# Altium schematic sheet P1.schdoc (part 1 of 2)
size 743 x 524 mm; Symbol: Drawing-Symbol_A4; @Project Name: pcbgolf; @Page Count: 1; @Update Date: 2026-09-13; @Create Date: 2026-09-12; @Schematic Name: Schematic1; @Page No: 1; @Page Name: P1; Company: EasyEDA.com; Version: eda image copy occupy; Page Size: A4; @Create Time: 18:56:01; @Update Time: 00:26:01; Border: 1; Width: 2925; Height: 2063; Region Start: 1; X Region Count: 6; Y Region Count: 4; Blade Width: 10; Title Block Position: 3; @Board Name: Board1; Device: Drawing-Symbol_A4
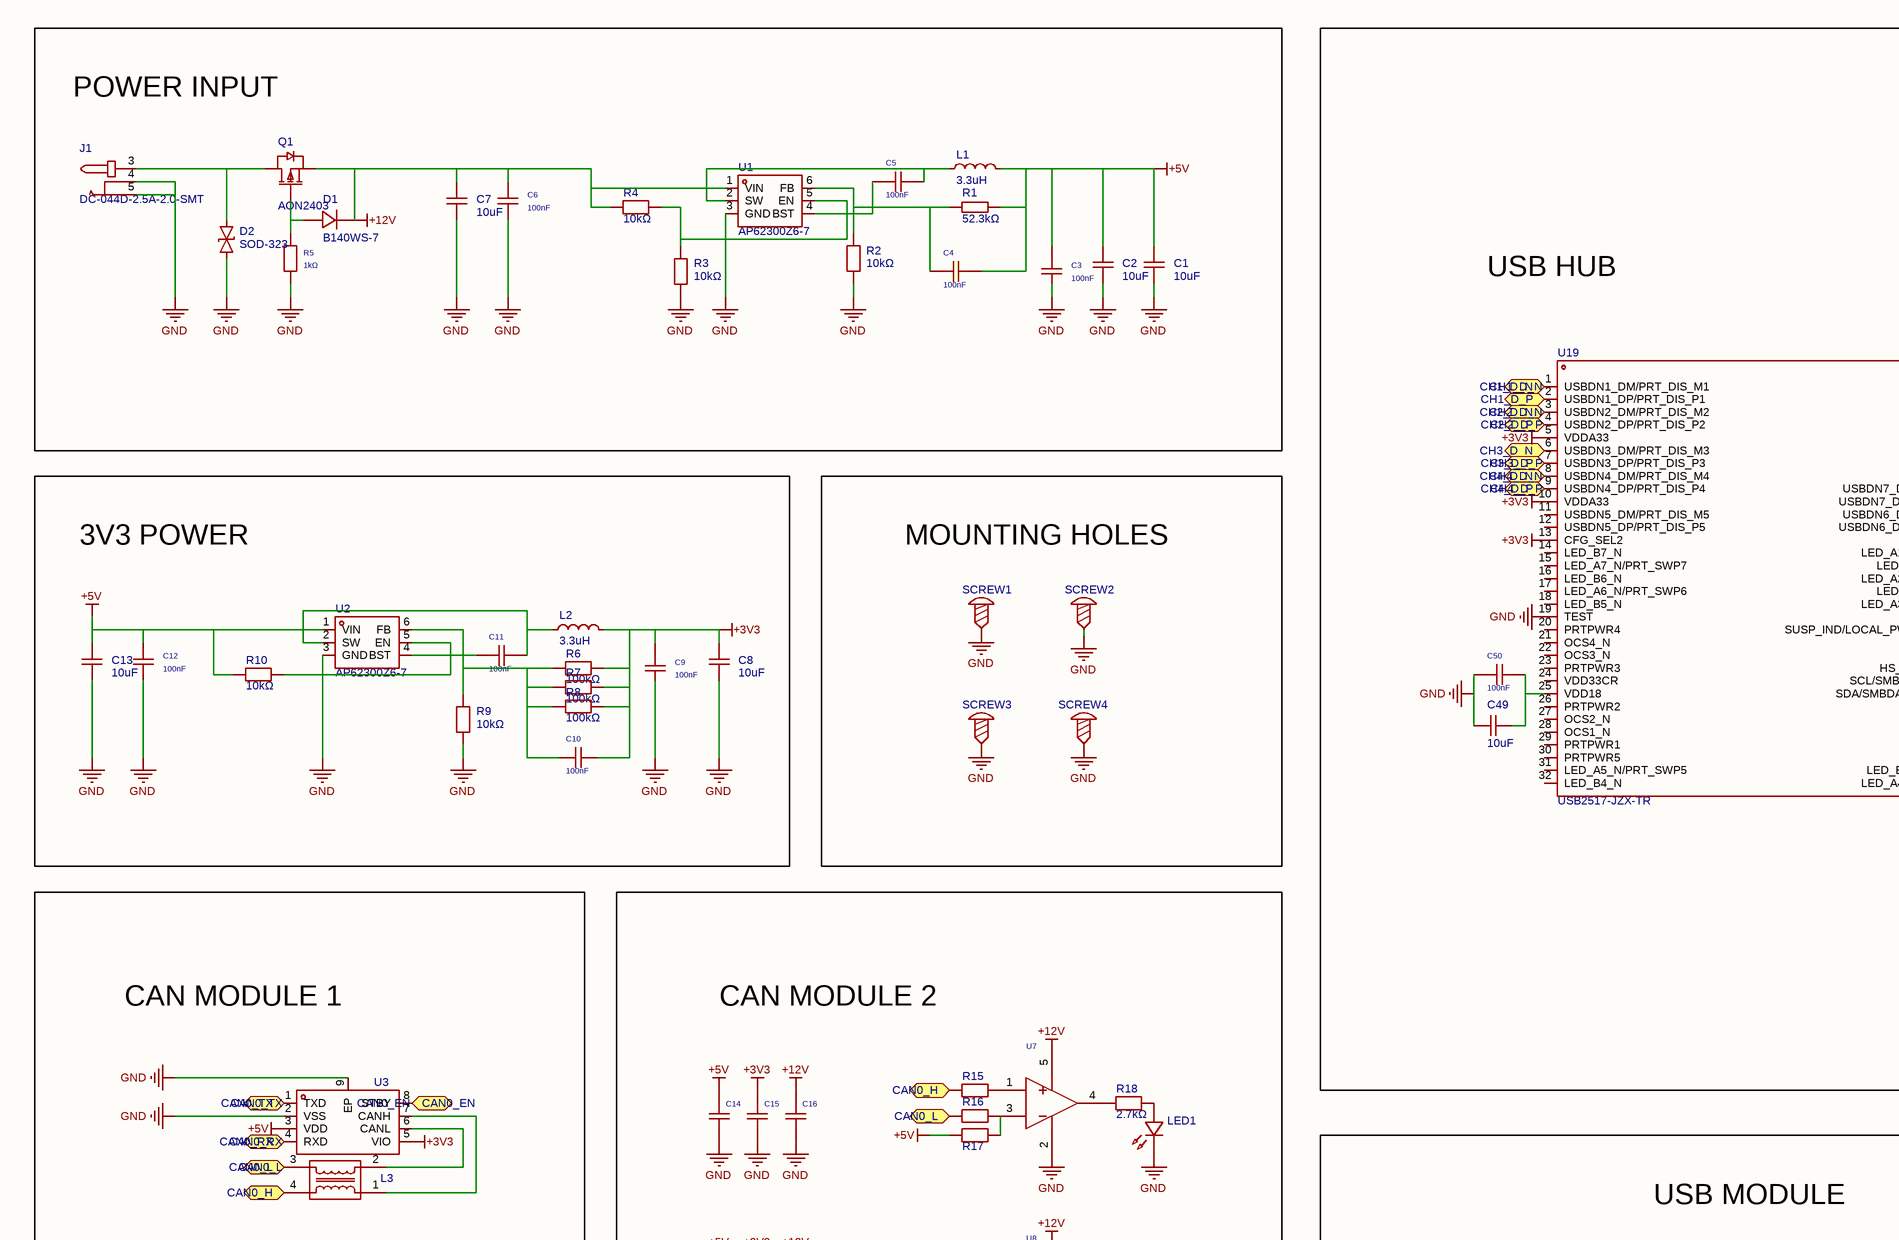
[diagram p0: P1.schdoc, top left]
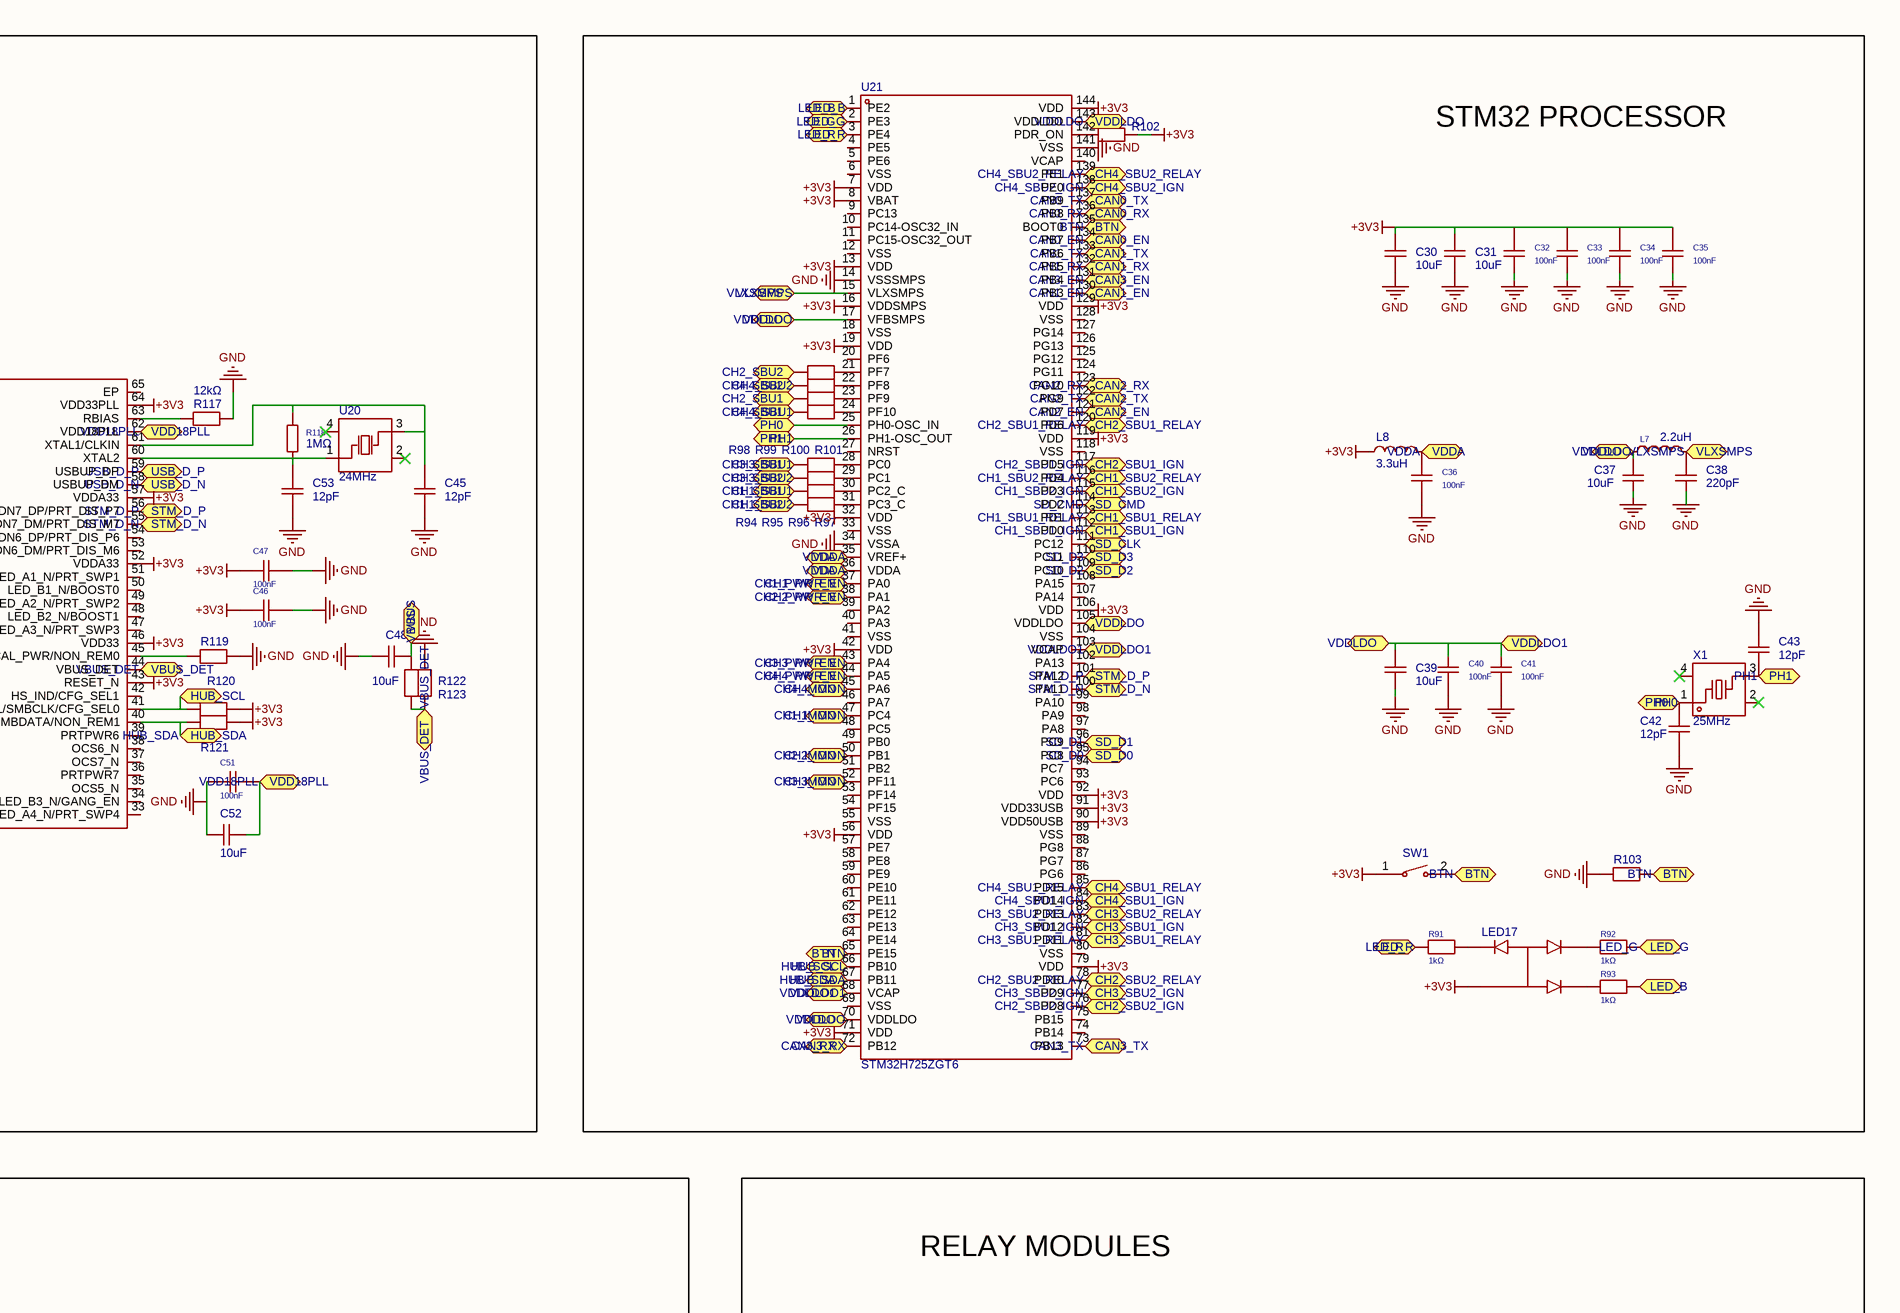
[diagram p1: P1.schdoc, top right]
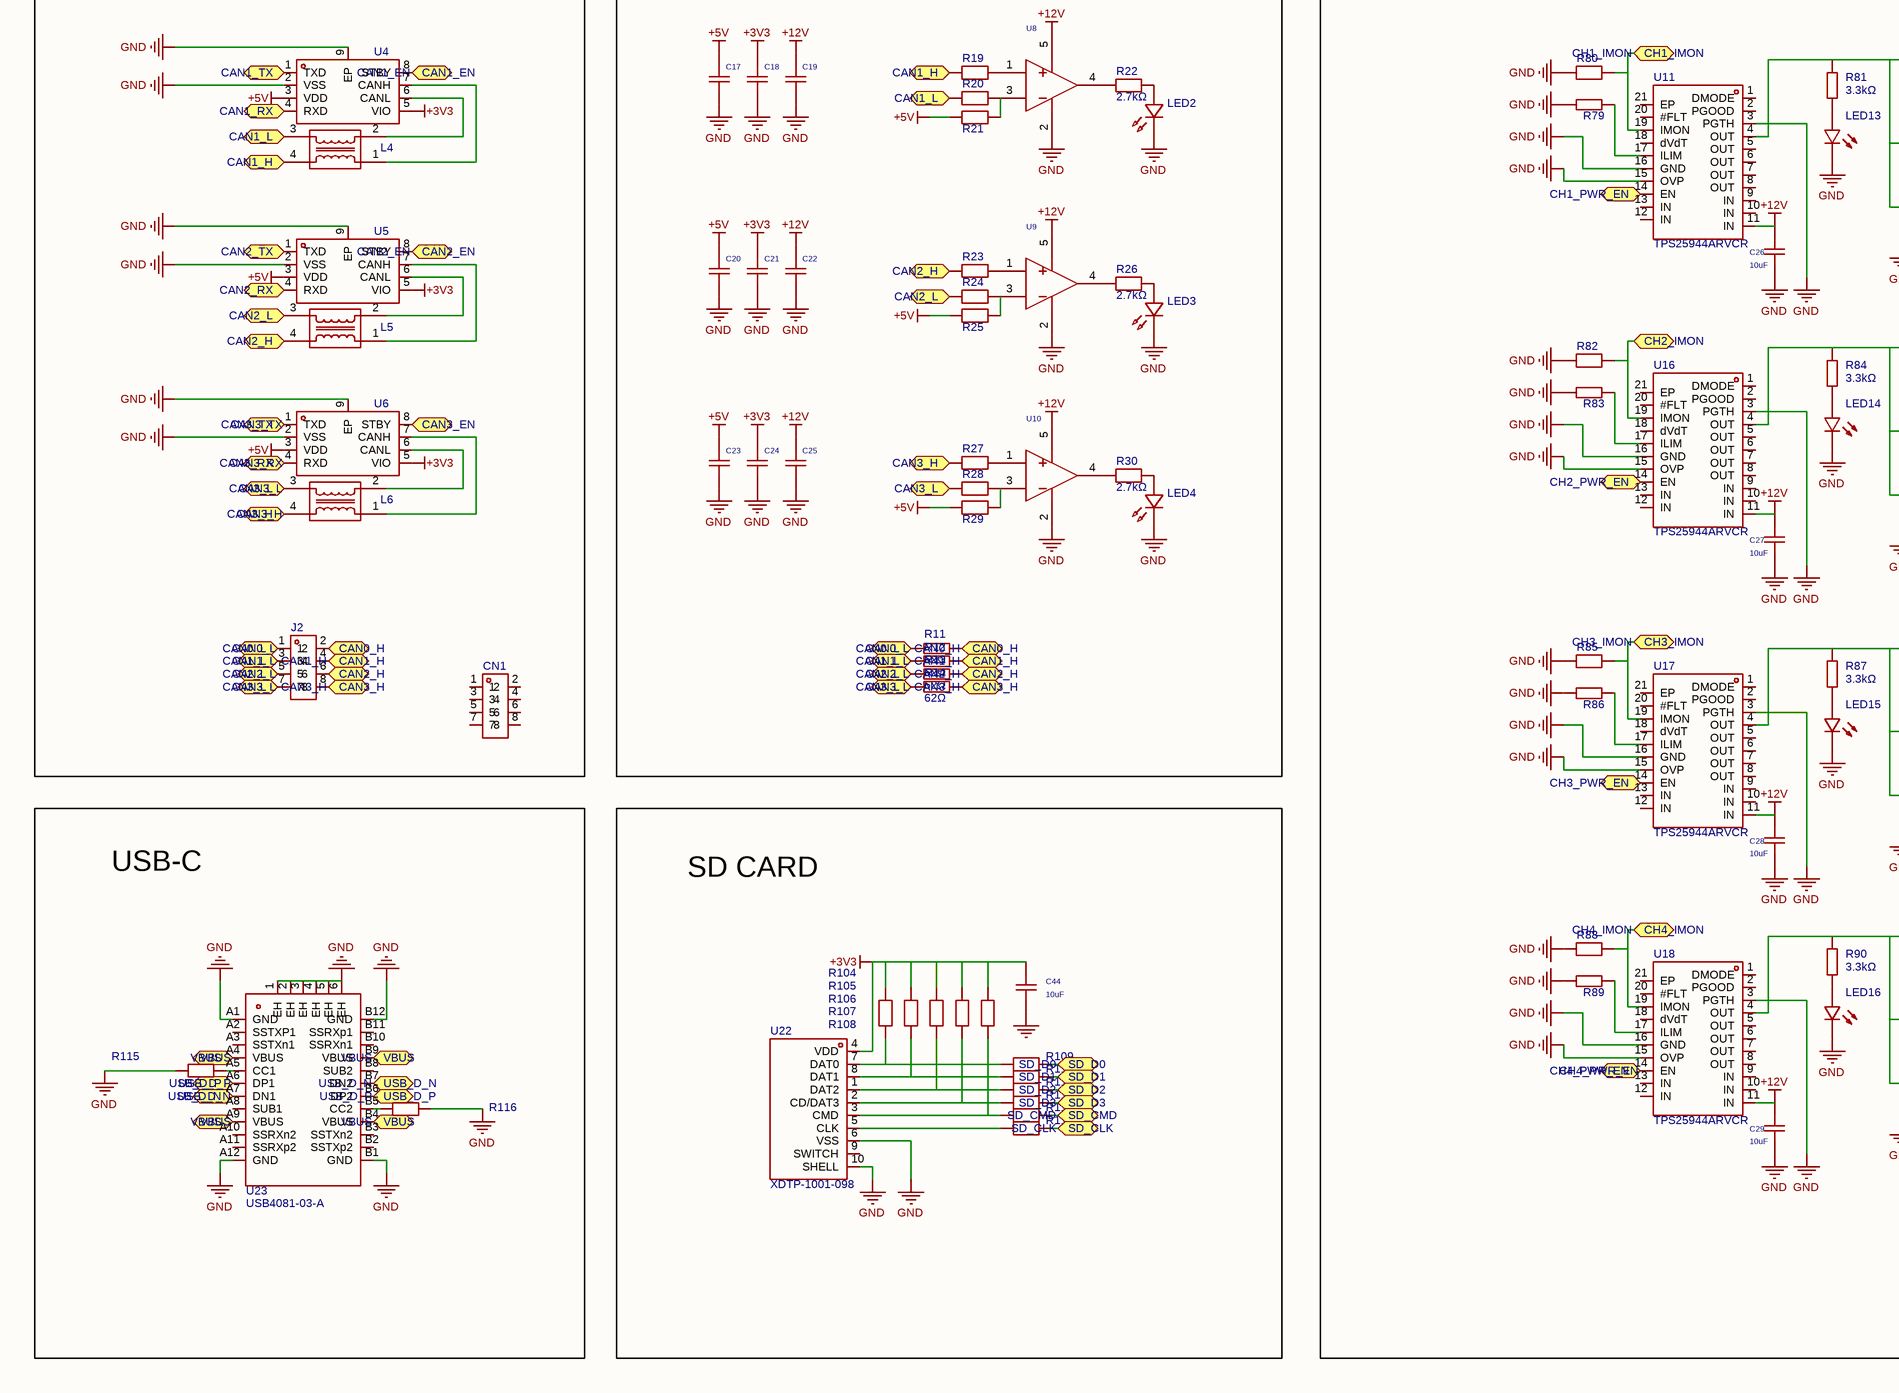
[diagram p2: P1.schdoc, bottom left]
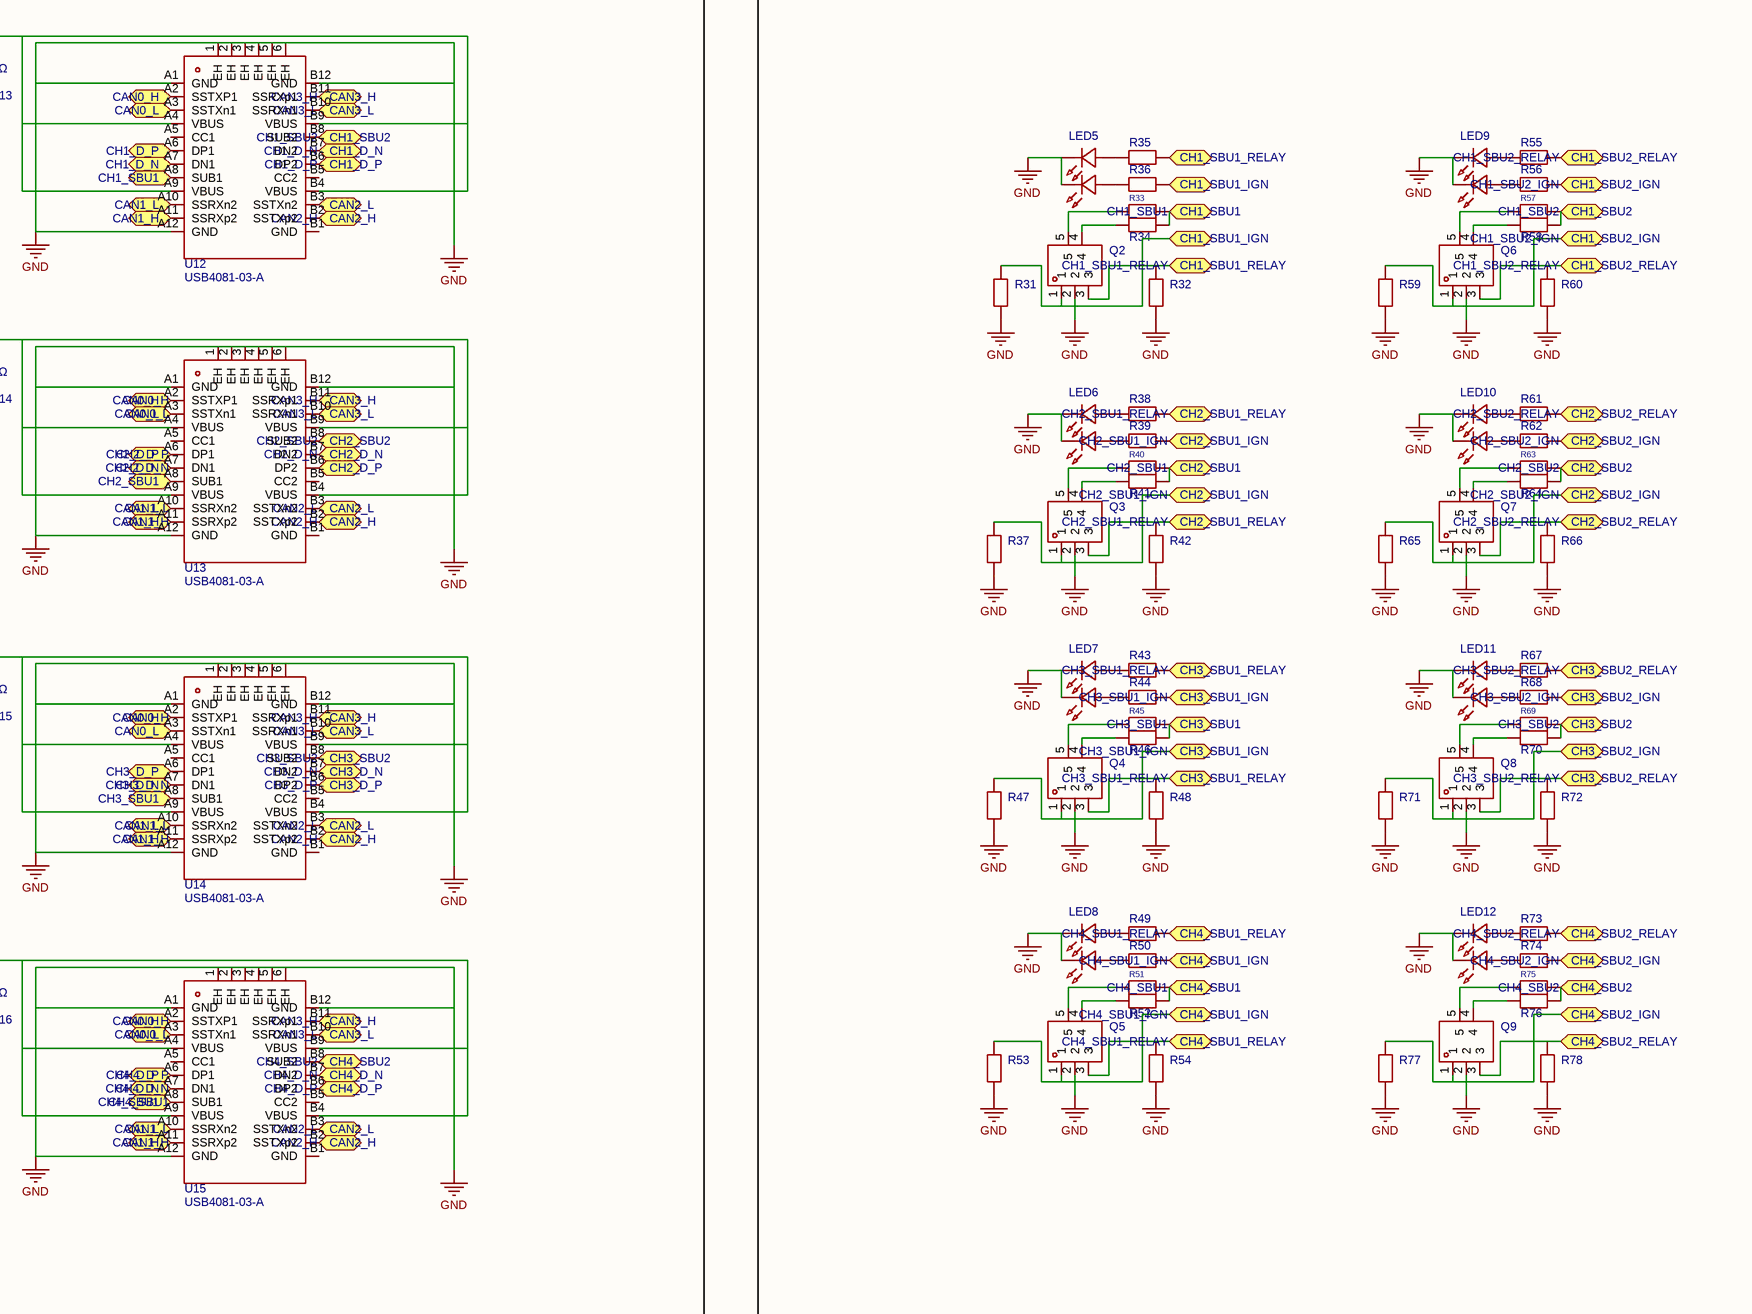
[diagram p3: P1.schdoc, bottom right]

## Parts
C1  10uF  [C0402]
C2  10uF  [C0402]
C3  100nF  [C0201]
C4  100nF  [C0201]
C5  100nF  [C0201]
C6  100nF  [C0201]
C7  10uF  [C0402]
C8  10uF  [C0402]
C9  100nF  [C0201]
C10  100nF  [C0201]
C11  100nF  [C0201]
C12  100nF  [C0201]
C13  10uF  [C0402]
C14  100nF  [C0201]  (value not drawn)
C15  100nF  [C0201]  (value not drawn)
C16  100nF  [C0201]  (value not drawn)
C17  100nF  [C0201]  (value not drawn)
C18  100nF  [C0201]  (value not drawn)
C19  100nF  [C0201]  (value not drawn)
C20  100nF  [C0201]  (value not drawn)
C21  100nF  [C0201]  (value not drawn)
C22  100nF  [C0201]  (value not drawn)
C23  100nF  [C0201]  (value not drawn)
C24  100nF  [C0201]  (value not drawn)
C25  100nF  [C0201]  (value not drawn)
C26  10uF  [C0201]
C27  10uF  [C0201]
C28  10uF  [C0201]
C29  10uF  [C0201]
C30  10uF  [C0402]
C31  10uF  [C0402]
C32  100nF  [C0201]
C33  100nF  [C0201]
C34  100nF  [C0201]
C35  100nF  [C0201]
C36  100nF  [C0201]
C37  10uF  [C0402]
C38  220pF  [C0201]
C39  10uF  [C0402]
C40  100nF  [C0201]
C41  100nF  [C0201]
C42  12pF  [C0201]
C43  12pF  [C0201]
C44  10uF  [C0201]
C45  12pF  [C0201]
C46  100nF  [C0201]
C47  100nF  [C0201]
C48  10uF  [C0402]
C49  10uF  [C0402]
C50  100nF  [C0201]
C51  100nF  [C0201]
C52  10uF  [C0402]
C53  12pF  [C0201]
CN1  DIP2*4P双排弯脚排母间距2.0mm塑长6.35塑高4.0ROHS散装  [HDR-TH_8P-P2.54_C9900016769]  (value not drawn)
D1  B140WS-7  [SOD-323_L1.8-W1.3-LS2.5-RD]
D2  SOD-323  [SOD-323_L1.7-W1.3-LS2.5-BI]
J1  DC-044D-2.5A-2.0-SMT  [DC-IN-SMD_DC-044D-2.5A-2.0-SMT]
J2  SSQ-104-04-T-D  [HDR-TH_8P-P2.54_SSW-104-23-F-D]  (value not drawn)
L1  3.3uH  [L0603]
L2  3.3uH  [L0603]
L3  ACM2012-900-2P-T001  [FILTER-SMD_4P-L2.0-W1.2-TL_ACM2012E]  (value not drawn)
L4  ACM2012-900-2P-T001  [FILTER-SMD_4P-L2.0-W1.2-TL_ACM2012E]  (value not drawn)
L5  ACM2012-900-2P-T001  [FILTER-SMD_4P-L2.0-W1.2-TL_ACM2012E]  (value not drawn)
L6  ACM2012-900-2P-T001  [FILTER-SMD_4P-L2.0-W1.2-TL_ACM2012E]  (value not drawn)
L7  2.2uH  [L0402]
L8  3.3uH  [L0603]
LED1  APHHS1005LSECK/J3-PF  [LED0402-RD_RED]  (value not drawn)
LED2  APHHS1005LSECK/J3-PF  [LED0402-RD_RED]  (value not drawn)
LED3  APHHS1005LSECK/J3-PF  [LED0402-RD_RED]  (value not drawn)
LED4  APHHS1005LSECK/J3-PF  [LED0402-RD_RED]  (value not drawn)
LED5  HSMF-C163  [LED-SMD_L1.6-W0.8_HSMF-C163]  (value not drawn)
LED6  HSMF-C163  [LED-SMD_L1.6-W0.8_HSMF-C163]  (value not drawn)
LED7  HSMF-C163  [LED-SMD_L1.6-W0.8_HSMF-C163]  (value not drawn)
LED8  HSMF-C163  [LED-SMD_L1.6-W0.8_HSMF-C163]  (value not drawn)
LED9  HSMF-C163  [LED-SMD_L1.6-W0.8_HSMF-C163]  (value not drawn)
LED10  HSMF-C163  [LED-SMD_L1.6-W0.8_HSMF-C163]  (value not drawn)
LED11  HSMF-C163  [LED-SMD_L1.6-W0.8_HSMF-C163]  (value not drawn)
LED12  HSMF-C163  [LED-SMD_L1.6-W0.8_HSMF-C163]  (value not drawn)
LED13  SLED-0603-H0_8MM  [LED0603-R-RD_RED]  (value not drawn)
LED14  SLED-0603-H0_8MM  [LED0603-R-RD_RED]  (value not drawn)
LED15  SLED-0603-H0_8MM  [LED0603-R-RD_RED]  (value not drawn)
LED16  SLED-0603-H0_8MM  [LED0603-R-RD_RED]  (value not drawn)
LED17  TZ1615RGB3U-Common Yang  [LED-SMD_TZ1615RGB3U-COMMON-YANG]  (value not drawn)
Q1  AON2403  [DFN-6_L2.0-W2.0-P0.65-BL-EP-1]
Q2  QS5K2TR  [SOT-23-5_L2.9-W1.6-P0.95-LS2.8-TL]  (value not drawn)
Q3  QS5K2TR  [SOT-23-5_L2.9-W1.6-P0.95-LS2.8-TL]  (value not drawn)
Q4  QS5K2TR  [SOT-23-5_L2.9-W1.6-P0.95-LS2.8-TL]  (value not drawn)
Q5  QS5K2TR  [SOT-23-5_L2.9-W1.6-P0.95-LS2.8-TL]  (value not drawn)
Q6  QS5K2TR  [SOT-23-5_L2.9-W1.6-P0.95-LS2.8-TL]  (value not drawn)
Q7  QS5K2TR  [SOT-23-5_L2.9-W1.6-P0.95-LS2.8-TL]  (value not drawn)
Q8  QS5K2TR  [SOT-23-5_L2.9-W1.6-P0.95-LS2.8-TL]  (value not drawn)
Q9  QS5K2TR  [SOT-23-5_L2.9-W1.6-P0.95-LS2.8-TL]  (value not drawn)
R1  52.3kΩ  [R0201]
R2  10kΩ  [R0201]
R3  10kΩ  [R0201]
R4  10kΩ  [R0201]
R5  1kΩ  [R0201]
R6  100kΩ  [R0201]
R7  100kΩ  [R0201]
R8  100kΩ  [R0201]
R9  10kΩ  [R0201]
R10  10kΩ  [R0201]
R11  62Ω  [R0201]
R12  62Ω  [R0201]
R13  62Ω  [R0201]
R14  62Ω  [R0201]
R15  10kΩ  [R0201]  (value not drawn)
R16  10kΩ  [R0201]  (value not drawn)
R17  100kΩ  [R0201]  (value not drawn)
R18  2.7kΩ  [R0201]
R19  10kΩ  [R0201]  (value not drawn)
R20  10kΩ  [R0201]  (value not drawn)
R21  100kΩ  [R0201]  (value not drawn)
R22  2.7kΩ  [R0201]
R23  10kΩ  [R0201]  (value not drawn)
R24  10kΩ  [R0201]  (value not drawn)
R25  100kΩ  [R0201]  (value not drawn)
R26  2.7kΩ  [R0201]
R27  10kΩ  [R0201]  (value not drawn)
R28  10kΩ  [R0201]  (value not drawn)
R29  100kΩ  [R0201]  (value not drawn)
R30  2.7kΩ  [R0201]
R31  10kΩ  [R0201]  (value not drawn)
R32  10kΩ  [R0201]  (value not drawn)
R33  1kΩ  [R0201]  (value not drawn)
R34  100Ω  [R0201]  (value not drawn)
R35  100Ω  [R0201]  (value not drawn)
R36  100Ω  [R0201]  (value not drawn)
R37  10kΩ  [R0201]  (value not drawn)
R38  100Ω  [R0201]  (value not drawn)
R39  100Ω  [R0201]  (value not drawn)
R40  1kΩ  [R0201]  (value not drawn)
R41  100Ω  [R0201]  (value not drawn)
R42  10kΩ  [R0201]  (value not drawn)
R43  100Ω  [R0201]  (value not drawn)
R44  100Ω  [R0201]  (value not drawn)
R45  1kΩ  [R0201]  (value not drawn)
R46  100Ω  [R0201]  (value not drawn)
R47  10kΩ  [R0201]  (value not drawn)
R48  10kΩ  [R0201]  (value not drawn)
R49  100Ω  [R0201]  (value not drawn)
R50  100Ω  [R0201]  (value not drawn)
R51  1kΩ  [R0201]  (value not drawn)
R52  100Ω  [R0201]  (value not drawn)
R53  10kΩ  [R0201]  (value not drawn)
R54  10kΩ  [R0201]  (value not drawn)
R55  100Ω  [R0201]  (value not drawn)
R56  100Ω  [R0201]  (value not drawn)
R57  1kΩ  [R0201]  (value not drawn)
R58  100Ω  [R0201]  (value not drawn)
R59  10kΩ  [R0201]  (value not drawn)
R60  10kΩ  [R0201]  (value not drawn)
R61  100Ω  [R0201]  (value not drawn)
R62  100Ω  [R0201]  (value not drawn)
R63  1kΩ  [R0201]  (value not drawn)
R64  100Ω  [R0201]  (value not drawn)
R65  10kΩ  [R0201]  (value not drawn)
R66  10kΩ  [R0201]  (value not drawn)
R67  100Ω  [R0201]  (value not drawn)
R68  100Ω  [R0201]  (value not drawn)
R69  1kΩ  [R0201]  (value not drawn)
R70  100Ω  [R0201]  (value not drawn)
R71  10kΩ  [R0201]  (value not drawn)
R72  10kΩ  [R0201]  (value not drawn)
R73  100Ω  [R0201]  (value not drawn)
R74  100Ω  [R0201]  (value not drawn)
R75  1kΩ  [R0201]  (value not drawn)
R76  100Ω  [R0201]  (value not drawn)
R77  10kΩ  [R0201]  (value not drawn)
R78  10kΩ  [R0201]  (value not drawn)
R79  28kΩ  [R0201]  (value not drawn)
R80  33kΩ  [R0201]  (value not drawn)
R81  3.3kΩ  [R0201]
R82  33kΩ  [R0201]  (value not drawn)
R83  28kΩ  [R0201]  (value not drawn)
R84  3.3kΩ  [R0201]
R85  33kΩ  [R0201]  (value not drawn)
R86  28kΩ  [R0201]  (value not drawn)
R87  3.3kΩ  [R0201]
R88  33kΩ  [R0201]  (value not drawn)
R89  28kΩ  [R0201]  (value not drawn)
R90  3.3kΩ  [R0201]
R91  1kΩ  [R0201]
R92  1kΩ  [R0201]
R93  1kΩ  [R0201]
R94  100kΩ  [R0201]  (value not drawn)
R95  100kΩ  [R0201]  (value not drawn)
R96  100kΩ  [R0201]  (value not drawn)
R97  100kΩ  [R0201]  (value not drawn)
R98  100kΩ  [R0201]  (value not drawn)
R99  100kΩ  [R0201]  (value not drawn)
R100  100kΩ  [R0201]  (value not drawn)
R101  100kΩ  [R0201]  (value not drawn)
R102  10kΩ  [R0201]  (value not drawn)
R103  10kΩ  [R0201]  (value not drawn)
R104  10kΩ  [R0201]  (value not drawn)
R105  10kΩ  [R0201]  (value not drawn)
R106  10kΩ  [R0201]  (value not drawn)
R107  10kΩ  [R0201]  (value not drawn)
R108  10kΩ  [R0201]  (value not drawn)
R109  0Ω  [R0201]  (value not drawn)
R110  0Ω  [R0201]  (value not drawn)
R111  0Ω  [R0201]  (value not drawn)
R112  0Ω  [R0201]  (value not drawn)
R113  0Ω  [R0201]  (value not drawn)
R114  0Ω  [R0201]  (value not drawn)
R115  10kΩ  [R0201]  (value not drawn)
R116  10kΩ  [R0201]  (value not drawn)
R117  12kΩ  [R0201]
R118  1MΩ  [R0402]
R119  10kΩ  [R0201]  (value not drawn)
R120  10kΩ  [R0201]  (value not drawn)
R121  10kΩ  [R0201]  (value not drawn)
R122  100kΩ  [R0201]  (value not drawn)
R123  100kΩ  [R0201]  (value not drawn)
SCREW1  (no value)  [Screw-Hole-M2]
SCREW2  (no value)  [Screw-Hole-M2]
SCREW3  (no value)  [Screw-Hole-M2]
SCREW4  (no value)  [Screw-Hole-M2]
SW1  TS-1809-T20  [SW-SMD_L3.9-W2.9-LS4.8SWQC_SPST]  (value not drawn)
U1  AP62300Z6-7  [SOT-563-6_L1.6-W1.2-P0.50-LS1.6-BL]
U2  AP62300Z6-7  [SOT-563-6_L1.6-W1.2-P0.50-LS1.6-BL]
U3  MCP2542FDT-E/MNY  [TDFN-8_L3.0-W2.0-P0.50-TL-EP]  (value not drawn)
U4  MCP2542FDT-E/MNY  [TDFN-8_L3.0-W2.0-P0.50-TL-EP]  (value not drawn)
U5  MCP2542FDT-E/MNY  [TDFN-8_L3.0-W2.0-P0.50-TL-EP]  (value not drawn)
U6  MCP2542FDT-E/MNY  [TDFN-8_L3.0-W2.0-P0.50-TL-EP]  (value not drawn)
U7  NCS20071XV53T2G  [SOT-553-5_L1.6-W1.2-P0.50-LS1.6-BL]  (value not drawn)
U8  NCS20071XV53T2G  [SOT-553-5_L1.6-W1.2-P0.50-LS1.6-BL]  (value not drawn)
U9  NCS20071XV53T2G  [SOT-553-5_L1.6-W1.2-P0.50-LS1.6-BL]  (value not drawn)
U10  NCS20071XV53T2G  [SOT-553-5_L1.6-W1.2-P0.50-LS1.6-BL]  (value not drawn)
U11  TPS25944ARVCR  [WQFN-20_L4.0-W3.0-P0.50-BL-EP]
U12  USB4081-03-A  [USB-SMD_USB4081-03-A]
U13  USB4081-03-A  [USB-SMD_USB4081-03-A]
U14  USB4081-03-A  [USB-SMD_USB4081-03-A]
U15  USB4081-03-A  [USB-SMD_USB4081-03-A]
U16  TPS25944ARVCR  [WQFN-20_L4.0-W3.0-P0.50-BL-EP]
U17  TPS25944ARVCR  [WQFN-20_L4.0-W3.0-P0.50-BL-EP]
U18  TPS25944ARVCR  [WQFN-20_L4.0-W3.0-P0.50-BL-EP]
U19  USB2517-JZX-TR  [QFN-64_L9.0-W9.0-P0.50-BL-EP4.8]
U20  24MHz  [CRYSTAL-SMD_4P-L3.2-W2.5-BL]
U21  STM32H725ZGT6  [LQFP-144_L20.0-W20.0-P0.50-LS22.0-BL]
U22  XDTP-1001-098  [MICRO-SD-SMD_XDTP-1001-098]
U23  USB4081-03-A  [USB-SMD_USB4081-03-A]
X1  25MHz  [CRYSTAL-SMD_4P-L2.0-W1.6-BL]

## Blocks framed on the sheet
POWER INPUT: C1-C7 D1 D2 J1 L1 Q1 R1-R5 U1
USB HUB: C45-C53 R117-R123 U19 U20
STM32 PROCESSOR: C30-C43 L7 L8 LED17 R91-R103 SW1 U21 X1
3V3 POWER: C8-C13 L2 R6-R10 U2
MOUNTING HOLES: SCREW1-SCREW4
CAN MODULE 1: CN1 J2 L3-L6 U3-U6
CAN MODULE 2: C14-C25 LED1-LED4 R11-R30 U7-U10
USB MODULE: C26-C29 LED13-LED16 R79-R90 U11-U18
RELAY MODULES: LED5-LED12 Q2-Q9 R31-R78
USB-C: R115 R116 U23
SD CARD: C44 R104-R114 U22

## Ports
BTN (bidir), CAN0_EN (bidir), CAN0_H (bidir), CAN0_L (bidir), CAN0_RX (bidir), CAN0_TX (bidir), CAN1_EN (bidir), CAN1_H (bidir), CAN1_L (bidir), CAN1_RX (bidir), CAN1_TX (bidir), CAN2_EN (bidir), CAN2_H (bidir), CAN2_L (bidir), CAN2_RX (bidir), CAN2_TX (bidir), CAN3_EN (bidir), CAN3_H (bidir), CAN3_L (bidir), CAN3_RX (bidir), CAN3_TX (bidir), CH1_D_N (bidir), CH1_D_P (bidir), CH1_IMON (bidir), CH1_PWR_EN (bidir), CH1_SBU1 (bidir), CH1_SBU1_IGN (bidir), CH1_SBU1_RELAY (bidir), CH1_SBU2 (bidir), CH1_SBU2_IGN (bidir), CH1_SBU2_RELAY (bidir), CH2_D_N (bidir), CH2_D_P (bidir), CH2_IMON (bidir), CH2_PWR_EN (bidir), CH2_SBU1 (bidir), CH2_SBU1_IGN (bidir), CH2_SBU1_RELAY (bidir), CH2_SBU2 (bidir), CH2_SBU2_IGN (bidir), CH2_SBU2_RELAY (bidir), CH3_D_N (bidir), CH3_D_P (bidir), CH3_IMON (bidir), CH3_PWR_EN (bidir), CH3_SBU1 (bidir), CH3_SBU1_IGN (bidir), CH3_SBU1_RELAY (bidir), CH3_SBU2 (bidir), CH3_SBU2_IGN (bidir), CH3_SBU2_RELAY (bidir), CH4_D_N (bidir), CH4_D_P (bidir), CH4_IMON (bidir), CH4_PWR_EN (bidir), CH4_SBU1 (bidir), CH4_SBU1_IGN (bidir), CH4_SBU1_RELAY (bidir), CH4_SBU2 (bidir), CH4_SBU2_IGN (bidir), CH4_SBU2_RELAY (bidir), HUB_SCL (bidir), HUB_SDA (bidir), LED_B (bidir), LED_G (bidir), LED_R (bidir), PH0 (bidir), PH1 (bidir), SD_CLK (bidir), SD_CMD (bidir), SD_D0 (bidir), SD_D1 (bidir), SD_D2 (bidir), SD_D3 (bidir), STM_D_N (bidir), STM_D_P (bidir), USB_D_N (bidir), USB_D_P (bidir), VBUS (bidir), VBUS_DET (bidir), VDD18PLL (bidir), VDDA (bidir), VDDLDO1 (bidir), VDDLDO (bidir), VLXSMPS (bidir)

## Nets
+3V3: C8.2 C9.1 C10.2 C15.2 C18.2 C21.2 C24.2 C30.2 C31.2 C32.2 C33.2 C34.2 C35.2 C44.2 C46.2 C47.2 L2.2 L8.1 LED17.1(+) R6.2 R7.2 R8.2 R102.2 R104.2 R105.2 R106.2 R107.2 R108.2 R120.1 R121.1 SW1.1 U3.5(VIO) U4.5(VIO) U5.5(VIO) U6.5(VIO) U19.5(VDDA33) U19.10(VDDA33) U19.13(CFG_SEL2) U19.43(RESET_N) U19.46(VDD33) U19.52(VDDA33) U19.57(VDDA33) U19.64(VDD33PLL) U21.7(VDD) U21.8(VBAT) U21.13(VDD) U21.16(VDDSMPS) U21.19(VDD) U21.32(VDD) U21.42(VDD) U21.56(VDD) U21.71(VDD) U21.79(VDD) U21.90(VDD50USB) U21.91(VDD33USB) U21.92(VDD) U21.106(VDD) U21.119(VDD) U21.129(VDD) U21.144(VDD) U22.4(VDD)
+5V: C1.2 C2.2 C3.1 C4.2 C12.1 C13.2 C14.2 C17.2 C20.2 C23.2 L1.2 R1.2 R10.2 R17.2 R21.2 R25.2 R29.2 U2.1(VIN) U3.3(VDD) U4.3(VDD) U5.3(VDD) U6.3(VDD)
+12V: C6.1 C7.2 C16.2 C19.2 C22.2 C25.2 C26.2 C27.2 C28.2 C29.2 D1.1(K) Q1.4(S) Q1.8(S) R4.1 U1.1(VIN) U7.5(V+) U8.5(V+) U9.5(V+) U10.5(V+) U11.11(IN) U16.11(IN) U17.11(IN) U18.11(IN)
GND: C1.1 C2.1 C3.2 C6.2 C7.1 C8.1 C9.2 C12.2 C13.1 C14.1 C15.1 C16.1 C17.1 C18.1 C19.1 C20.1 C21.1 C22.1 C23.1 C24.1 C25.1 C26.1 C27.1 C28.1 C29.1 C30.1 C31.1 C32.1 C33.1 C34.1 C35.1 C36.1 C37.1 C38.2 C39.1 C40.1 C41.1 C42.2 C43.1 C44.1 C45.2 C46.1 C47.1 C48.1 C49.1 C50.1 C51.1 C52.1 C53.2 D2.2 J1.4 J1.5 LED1.1(K) LED2.1(K) LED3.1(K) LED4.1(K) LED5.3(K) LED5.4(K) LED6.3(K) LED6.4(K) LED7.3(K) LED7.4(K) LED8.3(K) LED8.4(K) LED9.3(K) LED9.4(K) LED10.3(K) LED10.4(K) LED11.3(K) LED11.4(K) LED12.3(K) LED12.4(K) LED13.2(C) LED14.2(C) LED15.2(C) LED16.2(C) Q2.2 Q3.2 Q4.2 Q5.2 Q6.2 Q7.2 Q8.2 Q9.2 R2.2 R3.2 R5.2 R9.1 R31.1 R32.1 R37.1 R42.1 R47.1 R48.1 R53.1 R54.1 R59.1 R60.1 R65.1 R66.1 R71.1 R72.1 R77.1 R78.1 R79.2 R80.2 R82.2 R83.2 R85.2 R86.2 R88.2 R89.2 R103.1 R115.2 R116.1 R117.2 R119.1 R123.2 SCREW1.1 SCREW2.1 SCREW3.1 SCREW4.1 U1.3(GND) U2.3(GND) U3.2(VSS) U3.9(EP) U4.2(VSS) U4.9(EP) U5.2(VSS) U5.9(EP) U6.2(VSS) U6.9(EP) U7.2(V-) U8.2(V-) U9.2(V-) U10.2(V-) U11.3(PGTH) U11.15(OVP) U11.16(GND) U12.1(EH) U12.2(EH) U12.3(EH) U12.4(EH) U12.5(EH) U12.6(EH) U12.A1(GND) U12.A12(GND) U12.B12(GND) U13.1(EH) U13.2(EH) U13.3(EH) U13.4(EH) U13.5(EH) U13.6(EH) U13.A1(GND) U13.A12(GND) U13.B12(GND) U14.1(EH) U14.2(EH) U14.3(EH) U14.4(EH) U14.5(EH) U14.6(EH) U14.A1(GND) U14.A12(GND) U14.B12(GND) U15.1(EH) U15.2(EH) U15.3(EH) U15.4(EH) U15.5(EH) U15.6(EH) U15.A1(GND) U15.A12(GND) U15.B12(GND) U16.3(PGTH) U16.15(OVP) U16.16(GND) U17.3(PGTH) U17.15(OVP) U17.16(GND) U18.3(PGTH) U18.15(OVP) U18.16(GND) U19.19(TEST) U21.14(VSSSMPS) U21.34(VSSA) U21.141(VSS) U22.6(VSS) U22.10(SHELL) U23.1(EH) U23.2(EH) U23.3(EH) U23.4(EH) U23.5(EH) U23.6(EH) U23.A1(GND) U23.A12(GND) U23.B1(GND) U23.B12(GND)
BTN: R103.2 SW1.2 U21.65(PE15) U21.135(BOOT0) ; port BTN
CAN0_EN: U3.8(STBY) U21.134(PB7) ; port CAN0_EN
CAN0_H: J2.2 L3.4 R11.2 R15.1 U12.A2(SSTXP1) U13.A2(SSTXP1) U14.A2(SSTXP1) U15.A2(SSTXP1) ; port CAN0_H
CAN0_L: J2.1 L3.3 R11.1 R16.1 U12.A3(SSTXn1) U13.A3(SSTXn1) U14.A3(SSTXn1) U15.A3(SSTXn1) ; port CAN0_L
CAN0_RX: U3.4(RXD) U21.136(PB8) ; port CAN0_RX
CAN0_TX: U3.1(TXD) U21.137(PB9) ; port CAN0_TX
CAN1_EN: U4.8(STBY) U21.130(PB3) ; port CAN1_EN
CAN1_H: J2.4 L4.4 R12.2 R19.1 U12.A11(SSRXp2) U13.A11(SSRXp2) U14.A11(SSRXp2) U15.A11(SSRXp2) ; port CAN1_H
CAN1_L: J2.3 L4.3 R12.1 R20.1 U12.A10(SSRXn2) U13.A10(SSRXn2) U14.A10(SSRXn2) U15.A10(SSRXn2) ; port CAN1_L
CAN1_RX: U4.4(RXD) U21.132(PB5) ; port CAN1_RX
CAN1_TX: U4.1(TXD) U21.133(PB6) ; port CAN1_TX
CAN2_EN: U5.8(STBY) U21.121(PD7) ; port CAN2_EN
CAN2_H: J2.6 L5.4 R13.2 R23.1 U12.B2(SSTXp2) U13.B2(SSTXp2) U14.B2(SSTXp2) U15.B2(SSTXp2) ; port CAN2_H
CAN2_L: J2.5 L5.3 R13.1 R24.1 U12.B3(SSTXn2) U13.B3(SSTXn2) U14.B3(SSTXn2) U15.B3(SSTXn2) ; port CAN2_L
CAN2_RX: U5.4(RXD) U21.123(PG10) ; port CAN2_RX
CAN2_TX: U5.1(TXD) U21.122(PG9) ; port CAN2_TX
CAN3_EN: U6.8(STBY) U21.131(PB4) ; port CAN3_EN
CAN3_H: J2.8 L6.4 R14.2 R27.1 U12.B11(SSRXp1) U13.B11(SSRXp1) U14.B11(SSRXp1) U15.B11(SSRXp1) ; port CAN3_H
CAN3_L: J2.7 L6.3 R14.1 R28.1 U12.B10(SSRXn1) U13.B10(SSRXn1) U14.B10(SSRXn1) U15.B10(SSRXn1) ; port CAN3_L
CAN3_RX: U6.4(RXD) U21.72(PB12) ; port CAN3_RX
CAN3_TX: U6.1(TXD) U21.73(PB13) ; port CAN3_TX
CH1_D_N: U12.A7(DN1) U12.B7(DN2) U19.1(USBDN1_DM/PRT_DIS_M1) ; port CH1_D_N
CH1_D_P: U12.A6(DP1) U12.B6(DP2) U19.2(USBDN1_DP/PRT_DIS_P1) ; port CH1_D_P
CH1_IMON: R80.1 U11.19(IMON) U21.47(PC4) ; port CH1_IMON
CH1_PWR_EN: U11.14(EN) U21.37(PA0) ; port CH1_PWR_EN
CH1_SBU1: R33.2 R34.2 R96.2 U12.A8(SUB1) ; port CH1_SBU1
CH1_SBU1_IGN: Q2.1 R31.2 R36.2 U21.112(PD0) ; port CH1_SBU1_IGN
CH1_SBU1_RELAY: Q2.3 R32.2 R35.2 U21.113(PD1) ; port CH1_SBU1_RELAY
CH1_SBU2: R57.2 R58.2 R97.2 U12.B8(SUB2) ; port CH1_SBU2
CH1_SBU2_IGN: Q6.1 R56.2 R59.2 U21.115(PD3) ; port CH1_SBU2_IGN
CH1_SBU2_RELAY: Q6.3 R55.2 R60.2 U21.116(PD4) ; port CH1_SBU2_RELAY
CH2_D_N: U13.A7(DN1) U13.B7(DN2) U19.3(USBDN2_DM/PRT_DIS_M2) ; port CH2_D_N
CH2_D_P: U13.A6(DP1) U13.B6(DP2) U19.4(USBDN2_DP/PRT_DIS_P2) ; port CH2_D_P
CH2_IMON: R82.1 U16.19(IMON) U21.50(PB1) ; port CH2_IMON
CH2_PWR_EN: U16.14(EN) U21.38(PA1) ; port CH2_PWR_EN
CH2_SBU1: R40.2 R41.2 R100.2 U13.A8(SUB1) ; port CH2_SBU1
CH2_SBU1_IGN: Q3.1 R37.2 R39.2 U21.117(PD5) ; port CH2_SBU1_IGN
CH2_SBU1_RELAY: Q3.3 R38.2 R42.2 U21.120(PD6) ; port CH2_SBU1_RELAY
CH2_SBU2: R63.2 R64.2 R98.2 U13.B8(SUB2) ; port CH2_SBU2
CH2_SBU2_IGN: Q7.1 R62.2 R65.2 U21.76(PD8) ; port CH2_SBU2_IGN
CH2_SBU2_RELAY: Q7.3 R61.2 R66.2 U21.78(PD10) ; port CH2_SBU2_RELAY
CH3_D_N: U14.A7(DN1) U14.B7(DN2) U19.6(USBDN3_DM/PRT_DIS_M3) ; port CH3_D_N
CH3_D_P: U14.A6(DP1) U14.B6(DP2) U19.7(USBDN3_DP/PRT_DIS_P3) ; port CH3_D_P
CH3_IMON: R85.1 U17.19(IMON) U21.52(PF11) ; port CH3_IMON
CH3_PWR_EN: U17.14(EN) U21.43(PA4) ; port CH3_PWR_EN
CH3_SBU1: R45.2 R46.2 R94.2 U14.A8(SUB1) ; port CH3_SBU1
CH3_SBU1_IGN: Q4.1 R44.2 R47.2 U21.82(PD12) ; port CH3_SBU1_IGN
CH3_SBU1_RELAY: Q4.3 R43.2 R48.2 U21.81(PD11) ; port CH3_SBU1_RELAY
CH3_SBU2: R69.2 R70.2 R95.2 U14.B8(SUB2) ; port CH3_SBU2
CH3_SBU2_IGN: Q8.1 R68.2 R71.2 U21.77(PD9) ; port CH3_SBU2_IGN
CH3_SBU2_RELAY: Q8.3 R67.2 R72.2 U21.83(PD13) ; port CH3_SBU2_RELAY
CH4_D_N: U15.A7(DN1) U15.B7(DN2) U19.8(USBDN4_DM/PRT_DIS_M4) ; port CH4_D_N
CH4_D_P: U15.A6(DP1) U15.B6(DP2) U19.9(USBDN4_DP/PRT_DIS_P4) ; port CH4_D_P
CH4_IMON: R88.1 U18.19(IMON) U21.45(PA6) ; port CH4_IMON
CH4_PWR_EN: U18.14(EN) U21.44(PA5) ; port CH4_PWR_EN
CH4_SBU1: R51.2 R52.2 R101.2 U15.A8(SUB1) ; port CH4_SBU1
CH4_SBU1_IGN: Q5.1 R50.2 R53.2 U21.84(PD14) ; port CH4_SBU1_IGN
CH4_SBU1_RELAY: Q5.3 R49.2 R54.2 U21.85(PD15) ; port CH4_SBU1_RELAY
CH4_SBU2: R75.2 R76.2 R99.2 U15.B8(SUB2) ; port CH4_SBU2
CH4_SBU2_IGN: Q9.1 R74.2 R77.2 U21.138(PE0) ; port CH4_SBU2_IGN
CH4_SBU2_RELAY: Q9.3 R73.2 R78.2 U21.139(PE1) ; port CH4_SBU2_RELAY
HUB_SCL: R120.2 U19.41(SCL/SMBCLK/CFG_SEL0) U21.66(PB10) ; port HUB_SCL
HUB_SDA: R121.2 U19.40(SDA/SMBDATA/NON_REM1) U21.67(PB11) ; port HUB_SDA
LED_B: R93.2 U21.1(PE2) ; port LED_B
LED_G: R92.2 U21.2(PE3) ; port LED_G
LED_R: R91.1 U21.3(PE4) ; port LED_R
PH0: C42.1 U21.25(PH0-OSC_IN) X1.1 ; port PH0
PH1: C43.2 U21.26(PH1-OSC_OUT) X1.3 ; port PH1
SD_CLK: R114.2 U21.111(PC12) ; port SD_CLK
SD_CMD: R113.2 U21.114(PD2) ; port SD_CMD
SD_D0: R109.2 U21.95(PC8) ; port SD_D0
SD_D1: R110.2 U21.96(PC9) ; port SD_D1
SD_D2: R111.2 U21.109(PC10) ; port SD_D2
SD_D3: R112.2 U21.110(PC11) ; port SD_D3
STM_D_N: U19.55(USBDN7_DM/PRT_DIS_M7) U21.100(PA11) ; port STM_D_N
STM_D_P: U19.56(USBDN7_DP/PRT_DIS_P7) U21.101(PA12) ; port STM_D_P
USB_D_N: U19.58(USBUP_DM) U23.A7(DN1) U23.B7(DN2) ; port USB_D_N
USB_D_P: U19.59(USBUP_DP) U23.A6(DP1) U23.B6(DP2) ; port USB_D_P
VBUS: C48.2 R122.1 U23.A4(VBUS) U23.A9(VBUS) U23.B4(VBUS) U23.B9(VBUS) ; port VBUS
VBUS_DET: R122.2 R123.1 U19.44(VBUS_DET) ; port VBUS_DET
VDD18PLL: C51.2 C52.2 U19.62(VDD18PLL) ; port VDD18PLL
VDDA: C36.2 L8.2 U21.35(VREF+) U21.36(VDDA) ; port VDDA
VDDLDO: C37.2 C39.2 C40.2 C41.2 L7.1 U21.17(VFBSMPS) U21.68(VCAP) U21.70(VDDLDO) U21.103(VCAP) U21.105(VDDLDO) U21.143(VDDLDO) ; port VDDLDO, port VDDLDO1  [also labelled VDDLDO1]
VLXSMPS: C38.1 L7.2 U21.15(VLXSMPS) ; port VLXSMPS
NetC4_1: C4.1 R1.1 R2.1 U1.6(FB)
NetC5_1: C5.1 U1.4(BST)
NetC5_2: C5.2 L1.1 U1.2(SW)
NetC10_1: C10.1 R6.1 R7.1 R8.1 R9.2 U2.6(FB)
NetC11_1: C11.1 U2.4(BST)
NetC11_2: C11.2 L2.1 U2.2(SW)
NetC45_1: C45.1 R118.2 U19.61(XTAL1/CLKIN) U20.3(OSC2)
NetC49_2: C49.2 C50.2 U19.25(VDD18)
NetC53_1: C53.1 R118.1 U19.60(XTAL2) U20.1(OSC1)
NetD1_2: D1.2(A) Q1.3(G) R5.1
NetD2_1: D2.1 J1.3 Q1.1(D) Q1.2(D) Q1.5(D) Q1.6(D) Q1.7(D)
NetL3_1: L3.1 U3.7(CANH)
NetL3_2: L3.2 U3.6(CANL)
NetL4_1: L4.1 U4.7(CANH)
NetL4_2: L4.2 U4.6(CANL)
NetL5_1: L5.1 U5.7(CANH)
NetL5_2: L5.2 U5.6(CANL)
NetL6_1: L6.1 U6.7(CANH)
NetL6_2: L6.2 U6.6(CANL)
NetLED1_2: LED1.2(A) R18.2
NetLED2_2: LED2.2(A) R22.2
NetLED3_2: LED3.2(A) R26.2
NetLED4_2: LED4.2(A) R30.2
NetLED5_1: LED5.1(A) R36.1
NetLED5_2: LED5.2(A) R35.1
NetLED6_1: LED6.1(A) R39.1
NetLED6_2: LED6.2(A) R38.1
NetLED7_1: LED7.1(A) R44.1
NetLED7_2: LED7.2(A) R43.1
NetLED8_1: LED8.1(A) R50.1
NetLED8_2: LED8.2(A) R49.1
NetLED9_1: LED9.1(A) R56.1
NetLED9_2: LED9.2(A) R55.1
NetLED10_1: LED10.1(A) R62.1
NetLED10_2: LED10.2(A) R61.1
NetLED11_1: LED11.1(A) R68.1
NetLED11_2: LED11.2(A) R67.1
NetLED12_1: LED12.1(A) R74.1
NetLED12_2: LED12.2(A) R73.1
NetLED13_1: LED13.1(A) R81.1
NetLED14_1: LED14.1(A) R84.1
NetLED15_1: LED15.1(A) R87.1
NetLED16_1: LED16.1(A) R90.1
NetLED17_2: LED17.2(R) R91.2
NetLED17_3: LED17.3(G) R92.1
NetLED17_4: LED17.4(B) R93.1
NetQ2_4: Q2.4 R34.1
NetQ2_5: Q2.5 R33.1
NetQ3_4: Q3.4 R41.1
NetQ3_5: Q3.5 R40.1
NetQ4_4: Q4.4 R46.1
NetQ4_5: Q4.5 R45.1
NetQ5_4: Q5.4 R52.1
NetQ5_5: Q5.5 R51.1
NetQ6_4: Q6.4 R58.1
NetQ6_5: Q6.5 R57.1
NetQ7_4: Q7.4 R64.1
NetQ7_5: Q7.5 R63.1
NetQ8_4: Q8.4 R70.1
NetQ8_5: Q8.5 R69.1
NetQ9_4: Q9.4 R76.1
NetQ9_5: Q9.5 R75.1
NetR3_1: R3.1 R4.2 U1.5(EN)
NetR10_1: R10.1 U2.5(EN)
NetR15_2: R15.2 U7.1(IN+)
NetR16_2: R16.2 R17.1 U7.3(IN-)
NetR18_1: R18.1 U7.4(OUT)
NetR19_2: R19.2 U8.1(IN+)
NetR20_2: R20.2 R21.1 U8.3(IN-)
NetR22_1: R22.1 U8.4(OUT)
NetR23_2: R23.2 U9.1(IN+)
NetR24_2: R24.2 R25.1 U9.3(IN-)
NetR26_1: R26.1 U9.4(OUT)
NetR27_2: R27.2 U10.1(IN+)
NetR28_2: R28.2 R29.1 U10.3(IN-)
NetR30_1: R30.1 U10.4(OUT)
NetR79_1: R79.1 U11.17(ILIM)
NetR81_2: R81.2 U11.4(OUT) U12.A4(VBUS) U12.A9(VBUS) U12.B4(VBUS) U12.B9(VBUS)
NetR83_1: R83.1 U16.17(ILIM)
NetR84_2: R84.2 U13.A4(VBUS) U13.A9(VBUS) U13.B4(VBUS) U13.B9(VBUS) U16.4(OUT)
NetR86_1: R86.1 U17.17(ILIM)
NetR87_2: R87.2 U14.A4(VBUS) U14.A9(VBUS) U14.B4(VBUS) U14.B9(VBUS) U17.4(OUT)
NetR89_1: R89.1 U18.17(ILIM)
NetR90_2: R90.2 U15.A4(VBUS) U15.A9(VBUS) U15.B4(VBUS) U15.B9(VBUS) U18.4(OUT)
NetR94_1: R94.1 U21.28(PC0)
NetR95_1: R95.1 U21.29(PC1)
NetR96_1: R96.1 U21.30(PC2_C)
NetR97_1: R97.1 U21.31(PC3_C)
NetR98_1: R98.1 U21.21(PF7)
NetR99_1: R99.1 U21.22(PF8)
NetR100_1: R100.1 U21.23(PF9)
NetR101_1: R101.1 U21.24(PF10)
NetR102_1: R102.1 U21.142(PDR_ON)
NetR104_1: R104.1 R109.1 U22.7(DAT0)
NetR105_1: R105.1 R110.1 U22.8(DAT1)
NetR106_1: R106.1 R111.1 U22.1(DAT2)
NetR107_1: R107.1 R112.1 U22.2(CD/DAT3)
NetR108_1: R108.1 R113.1 U22.3(CMD)
NetR114_1: R114.1 U22.5(CLK)
NetR115_1: R115.1 U23.A5(CC1)
NetR116_2: R116.2 U23.B5(CC2)
NetR117_1: R117.1 U19.63(RBIAS)
NetR119_2: R119.2 U19.45(SUSP_IND/LOCAL_PWR/NON_REM0)

Not connected (* = marked no-connect by the designer): CN1 1 2 3 4 5 6 7 8; U11 1(DMODE) 2(PGOOD) 5(OUT) 6(OUT) 7(OUT) 8(OUT) 9(IN) 10(IN) 12(IN) 13(IN) 18(dVdT) 20(#FLT) 21(EP); U12 A5(CC1) B1(GND) B5(CC2); U13 A5(CC1) B1(GND) B5(CC2); U14 A5(CC1) B1(GND) B5(CC2); U15 A5(CC1) B1(GND) B5(CC2); U16 1(DMODE) 2(PGOOD) 5(OUT) 6(OUT) 7(OUT) 8(OUT) 9(IN) 10(IN) 12(IN) 13(IN) 18(dVdT) 20(#FLT) 21(EP); U17 1(DMODE) 2(PGOOD) 5(OUT) 6(OUT) 7(OUT) 8(OUT) 9(IN) 10(IN) 12(IN) 13(IN) 18(dVdT) 20(#FLT) 21(EP); U18 1(DMODE) 2(PGOOD) 5(OUT) 6(OUT) 7(OUT) 8(OUT) 9(IN) 10(IN) 12(IN) 13(IN) 18(dVdT) 20(#FLT) 21(EP); U19 11(USBDN5_DM/PRT_DIS_M5) 12(USBDN5_DP/PRT_DIS_P5) 14(LED_B7_N) 15(LED_A7_N/PRT_SWP7) 16(LED_B6_N) 17(LED_A6_N/PRT_SWP6) 18(LED_B5_N) 20(PRTPWR4) 21(OCS4_N) 22(OCS3_N) 23(PRTPWR3) 24(VDD33CR) 26(PRTPWR2) 27(OCS2_N) 28(OCS1_N) 29(PRTPWR1) 30(PRTPWR5) 31(LED_A5_N/PRT_SWP5) 32(LED_B4_N) 33(LED_A4_N/PRT_SWP4) 34(LED_B3_N/GANG_EN) 35(OCS5_N) 36(PRTPWR7) 37(OCS7_N) 38(OCS6_N) 39(PRTPWR6) 42(HS_IND/CFG_SEL1) 47(LED_A3_N/PRT_SWP3) 48(LED_B2_N/BOOST1) 49(LED_A2_N/PRT_SWP2) 50(LED_B1_N/BOOST0) 51(LED_A1_N/PRT_SWP1) 53(USBDN6_DM/PRT_DIS_M6) 54(USBDN6_DP/PRT_DIS_P6) 65(EP); U20 2(GND)* 4(GND)*; U21 4(PE5) 5(PE6) 6(VSS) 9(PC13) 10(PC14-OSC32_IN) 11(PC15-OSC32_OUT) 12(VSS) 18(VSS) 20(PF6) 27(NRST) 33(VSS) 39(PA2) 40(PA3) 41(VSS) 46(PA7) 48(PC5) 49(PB0) 51(PB2) 53(PF14) 54(PF15) 55(VSS) 57(PE7) 58(PE8) 59(PE9) 60(PE10) 61(PE11) 62(PE12) 63(PE13) 64(PE14) 69(VSS) 74(PB14) 75(PB15) 80(VSS) 86(PG6) 87(PG7) 88(PG8) 89(VSS) 93(PC6) 94(PC7) 97(PA8) 98(PA9) 99(PA10) 102(PA13) 104(VSS) 107(PA14) 108(PA15) 118(VSS) 124(PG11) 125(PG12) 126(PG13) 127(PG14) 128(VSS) 140(VCAP); U22 9(SWITCH); U23 A2(SSTXP1) A3(SSTXn1) A8(SUB1) A10(SSRXn2) A11(SSRXp2) B2(SSTXp2) B3(SSTXn2) B8(SUB2) B10(SSRXn1) B11(SSRXp1); X1 2(GND)* 4(GND)*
